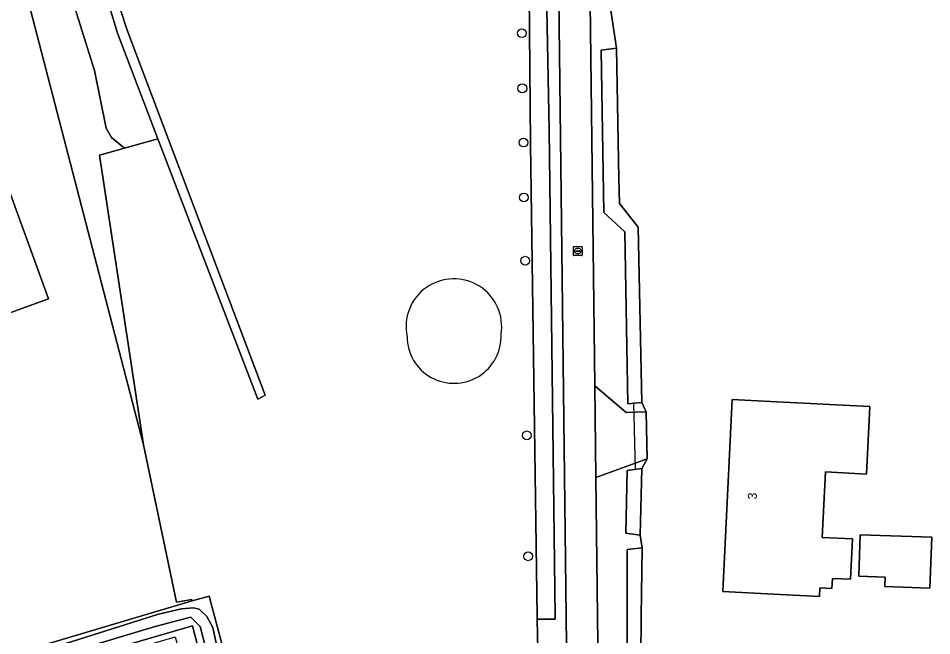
# Model space of a CAD drawing. Extents: x 163859 to 164644, y 379566 to 382155.
# Drawn here: x 164380.2 to 164482.6, y 381497.9 to 381567 of the extents above; entities that cross this region are included whole.
import ezdxf

# ---------------------------------------------------------------- set-up
doc = ezdxf.new("R2010")
doc.units = 0
for name, color, linetype in [('IMGEO_Boom', 7, 'Continuous'), ('IMGEO_Duiker', 7, 'Continuous'), ('IMGEO_Erf', 7, 'Continuous'), ('IMGEO_Grasland_overig', 7, 'Continuous'), ('IMGEO_Groenvoorziening', 7, 'Continuous'), ('IMGEO_Loofbos', 7, 'Continuous'), ('IMGEO_Oever', 7, 'Continuous'), ('IMGEO_Pand', 7, 'Continuous'), ('IMGEO_Pand_nummerreeks', 7, 'Continuous'), ('IMGEO_Rijbaan_lokaal_gesloten', 7, 'Continuous'), ('IMGEO_Rioolput', 7, 'Continuous'), ('IMGEO_Voetpad_open', 7, 'Continuous'), ('IMGEO_Waterloop', 7, 'Continuous')]:
    doc.layers.add(name, color=color, linetype=linetype)

msp = doc.modelspace()

# ---------------------------------------------------------------- linework, layer by layer
at = {"layer": 'IMGEO_Boom'}
for centre in [(164436.63, 381565.35), (164436.69, 381559.18), (164436.82, 381553.1), (164436.86, 381546.96), (164437, 381539.87), (164437.2, 381520.3), (164437.35, 381506.75)]:
    msp.add_circle(centre, 0.489, dxfattribs=at)
at = {"layer": 'IMGEO_Duiker'}
msp.add_lwpolyline([(164449.15, 381523.97), (164449.33, 381516.45)], dxfattribs=at)
at = {"layer": 'IMGEO_Erf'}
for points in [[(164445.79, 381598.85), (164445.76, 381596.44), (164445.96, 381592.66), (164445.85, 381586.66), (164445.92, 381582.44), (164446.04, 381571.66), (164447.24, 381563.68), (164447.52, 381549.09), (164447.58, 381546.29), (164449.66, 381543.61), (164450.08, 381523.98), (164450.55, 381522.92), (164450.68, 381517.67), (164450.07, 381516.57), (164449.91, 381509.12), (164450.1, 381507.69), (164450.01, 381500), (164449.96, 381495.46)], [(164380.24, 381495.98), (164399.71, 381501.75), (164399.68, 381501.92), (164397.93, 381501.62), (164394.23, 381519.23), (164377.05, 381585.25)]]:
    msp.add_lwpolyline(points, dxfattribs=at)
for points in [[(164367.06, 381553.7), (164375.84, 381556.9), (164383.59, 381535.61), (164374.81, 381532.42)], [(164473.46, 381504.17), (164471.43, 381504.27), (164471.38, 381503.14), (164470.04, 381503.2), (164470, 381502.26), (164464.14, 381502.55), (164459.15, 381502.79), (164460.21, 381524.3), (164465.2, 381524.06), (164475.64, 381523.54), (164475.26, 381515.97), (164470.65, 381516.2), (164470.29, 381508.86), (164473.68, 381508.69)], [(164482.36, 381503.18), (164477.29, 381503.36), (164477.33, 381504.41), (164474.39, 381504.51), (164474.55, 381509.16), (164482.56, 381508.89)]]:
    msp.add_lwpolyline(points, close=True, dxfattribs=at)
at = {"layer": 'IMGEO_Grasland_overig'}
for points in [[(164392.11, 381552.47), (164390.65, 381553.68), (164390.08, 381554.71), (164388.77, 381561.19), (164381.76, 381583.47), (164380.51, 381593.56), (164377.23, 381593.05), (164374.37, 381592.06), (164375.48, 381589.55), (164377.05, 381585.25), (164394.23, 381519.23), (164389.32, 381551.69)], [(164403.38, 381480.67), (164403.25, 381483.47), (164403.76, 381484.04), (164404.03, 381484.15), (164403.46, 381487.71), (164402.44, 381487.77), (164402.22, 381489.44), (164399.72, 381498.97), (164381.15, 381493.56), (164378.9, 381492.55), (164376.45, 381492.51), (164374.19, 381493.46), (164372.5, 381495.24), (164367, 381500.41), (164355.98, 381512.51), (164353.09, 381515.54), (164349.7, 381517.97), (164348.35, 381518.62), (164374.92, 381491), (164397.81, 381497.74), (164404.26, 381474.32)]]:
    msp.add_lwpolyline(points, close=True, dxfattribs=at)
at = {"layer": 'IMGEO_Groenvoorziening'}
for points in [[(164443.88, 381602.47), (164444.8, 381525.85), (164448.32, 381522.87), (164450.55, 381522.92), (164450.08, 381523.98), (164448.5, 381523.83), (164448.18, 381543.12), (164445.82, 381545.26), (164445.54, 381563.46), (164447.24, 381563.68), (164446.04, 381571.66)], [(164437.62, 381342.51), (164440.93, 381376.03), (164442.03, 381410.67), (164442.31, 381432.69), (164442.26, 381444.54), (164442.24, 381448.35), (164442.22, 381457.68), (164442.22, 381458.62), (164442.05, 381465.53), (164441.98, 381468.27), (164441.6, 381500), (164440.42, 381600.95)], [(164438.92, 381595.29), (164439.69, 381554.54), (164440.38, 381500), (164440.38, 381499.71), (164438.34, 381499.7), (164438.46, 381494.53)]]:
    msp.add_lwpolyline(points, dxfattribs=at)
for points in [[(164395.86, 381553.52), (164391.32, 381565.35), (164388.89, 381573.41), (164387.77, 381579.05), (164386.14, 381584.23), (164384.86, 381594.48), (164380.51, 381593.56), (164381.76, 381583.47), (164388.77, 381561.19), (164390.08, 381554.71), (164390.65, 381553.68), (164392.11, 381552.47)], [(164448.2, 381486.51), (164447.99, 381488.08), (164447.36, 381488.05), (164447.04, 381496.29), (164448.45, 381496.92), (164448.44, 381500), (164448.42, 381507.52), (164450.1, 381507.69), (164449.91, 381509.12), (164448.27, 381509.34), (164448.43, 381516.36), (164450.07, 381516.57), (164450.68, 381517.67), (164444.92, 381515.57), (164445.11, 381500), (164445.25, 381488.48)]]:
    msp.add_lwpolyline(points, close=True, dxfattribs=at)
for centre, radius, start, end in [((164429.02, 381532.48), 5.36, 350.5628, 192.1236), ((164429.04, 381531.4), 5.27, 180.5064, 2.18)]:
    msp.add_arc(centre, radius, start, end, dxfattribs=at)
at = {"layer": 'IMGEO_Loofbos'}
for points in [[(164438.46, 381494.53), (164438.34, 381499.7), (164438.34, 381500), (164437.6, 381552.99), (164437.24, 381595.18)], [(164388.41, 381582.72), (164390.02, 381574.06), (164391.09, 381569.85), (164392.41, 381565.7), (164407.87, 381524.82), (164407.05, 381524.34), (164395.86, 381553.52), (164392.11, 381552.47), (164389.32, 381551.69), (164394.23, 381519.23), (164397.93, 381501.62), (164399.68, 381501.92), (164399.71, 381501.75), (164401.6, 381502.3), (164404.9, 381489.96), (164405.2, 381487.7), (164404.81, 381487.67), (164403.46, 381487.71), (164404.03, 381484.15)]]:
    msp.add_lwpolyline(points, dxfattribs=at)
for centre, radius, start, end in [((164429.02, 381532.48), 5.36, 350.5628, 192.1236), ((164429.04, 381531.4), 5.27, 180.5064, 2.18)]:
    msp.add_arc(centre, radius, start, end, dxfattribs=at)
at = {"layer": 'IMGEO_Oever'}
for points in [[(164404.9, 381489.96), (164401.6, 381502.3), (164399.71, 381501.75), (164380.24, 381495.98)], [(164381.07, 381495.55), (164392.99, 381499.33), (164395.92, 381500.28), (164398.49, 381500.86), (164399.86, 381500.99), (164400.48, 381500.83), (164401.35, 381500), (164402, 381498.79), (164402.74, 381495.45)], [(164403.46, 381487.71), (164400.58, 381498.87), (164399.54, 381499.92), (164398.09, 381499.57), (164395.31, 381498.82), (164382.41, 381494.93)], [(164381.15, 381493.56), (164399.72, 381498.97), (164402.22, 381489.44)]]:
    msp.add_lwpolyline(points, dxfattribs=at)
at = {"layer": 'IMGEO_Pand'}
for points in [[(164374.81, 381532.42), (164383.59, 381535.61), (164375.84, 381556.9), (164367.06, 381553.7)], [(164470, 381502.26), (164470.04, 381503.2), (164471.38, 381503.14), (164471.43, 381504.27), (164473.46, 381504.17), (164473.68, 381508.69), (164470.29, 381508.86), (164470.65, 381516.2), (164475.26, 381515.97), (164475.64, 381523.54), (164465.2, 381524.06), (164460.21, 381524.3), (164459.15, 381502.79), (164464.14, 381502.55)], [(164474.39, 381504.51), (164477.33, 381504.41), (164477.29, 381503.36), (164482.36, 381503.18), (164482.56, 381508.89), (164474.55, 381509.16)]]:
    msp.add_lwpolyline(points, close=True, dxfattribs=at)
at = {"layer": 'IMGEO_Rijbaan_lokaal_gesloten'}
for points in [[(164445.42, 381474.39), (164445.36, 381478.81), (164445.25, 381488.48), (164445.11, 381500), (164444.92, 381515.57), (164444.8, 381525.85), (164443.88, 381602.47)], [(164440.42, 381600.95), (164441.6, 381500), (164441.98, 381468.27), (164442.05, 381465.53), (164442.22, 381458.62), (164442.22, 381457.68), (164445.79, 381457.7)]]:
    msp.add_lwpolyline(points, dxfattribs=at)
at = {"layer": 'IMGEO_Rioolput'}
for p, q in [((164442.41, 381540.52), (164442.41, 381541.38)), ((164442.48, 381541.45), (164443.33, 381541.45)), ((164442.89, 381541.23), (164442.92, 381541.23)), ((164443.41, 381541.38), (164443.41, 381540.52)), ((164443.33, 381540.45), (164442.48, 381540.45)), ((164442.66, 381540.94), (164442.66, 381540.96)), ((164443.1, 381540.91), (164442.7, 381540.91)), ((164442.71, 381540.99), (164443.1, 381540.99)), ((164442.92, 381540.67), (164442.89, 381540.67)), ((164443.15, 381540.96), (164443.15, 381540.94))]:
    msp.add_line(p, q, dxfattribs=at)
for points in [[(164442.41, 381540.52), (164442.41, 381541.38)], [(164442.48, 381541.45), (164443.33, 381541.45)], [(164443.41, 381541.38), (164443.41, 381540.52)], [(164443.33, 381540.45), (164442.48, 381540.45)]]:
    msp.add_lwpolyline(points, dxfattribs=at)
for centre, radius, start, end in [((164442.48, 381541.37), 0.0765, 91.552, 178.448), ((164442.48, 381541.37), 0.0765, 91.552, 178.448), ((164443.33, 381541.37), 0.0765, 1.552, 88.448), ((164443.33, 381541.37), 0.0765, 1.552, 88.448), ((164442.48, 381540.52), 0.0765, 181.552, 268.448), ((164442.48, 381540.52), 0.0765, 181.552, 268.448), ((164442.7, 381540.95), 0.0403, 85.8775, 175.7526), ((164442.7, 381540.94), 0.0366, 178.938, 274.7102), ((164443.11, 381540.95), 0.0386, 1.7309, 96.639), ((164443.11, 381540.95), 0.043, 264.8664, 352.4533), ((164443.33, 381540.52), 0.0765, 271.552, 358.448), ((164443.33, 381540.52), 0.0765, 271.552, 358.448)]:
    msp.add_arc(centre, radius, start, end, dxfattribs=at)
for centre, major_axis, ratio, start_param, end_param in [((164442.89, 381540.95), (-0.387, 0.002), 0.722429, 4.712389, 7.853982), ((164442.92, 381540.95), (-0.39, 0.002), 0.717154, 1.570796, 4.712389)]:
    msp.add_ellipse(centre, major_axis=major_axis, ratio=ratio, start_param=start_param, end_param=end_param, dxfattribs=at)
at = {"layer": 'IMGEO_Voetpad_open'}
msp.add_lwpolyline([(164444.8, 381525.85), (164444.92, 381515.57), (164450.68, 381517.67), (164450.55, 381522.92), (164448.32, 381522.87)], close=True, dxfattribs=at)
at = {"layer": 'IMGEO_Waterloop'}
for points in [[(164437.24, 381595.18), (164437.6, 381552.99), (164438.34, 381500), (164438.34, 381499.7), (164440.38, 381499.71), (164440.38, 381500), (164439.69, 381554.54)], [(164439.69, 381554.54), (164438.92, 381595.29)], [(164387.11, 381582.42), (164387.77, 381579.05), (164388.89, 381573.41), (164391.32, 381565.35), (164395.86, 381553.52), (164407.05, 381524.34), (164407.87, 381524.82), (164392.41, 381565.7), (164391.09, 381569.85), (164390.02, 381574.06), (164388.41, 381582.72)], [(164402.74, 381495.45), (164402, 381498.79), (164401.35, 381500), (164400.48, 381500.83), (164399.86, 381500.99), (164398.49, 381500.86), (164395.92, 381500.28), (164392.99, 381499.33), (164381.07, 381495.55)], [(164382.41, 381494.93), (164395.31, 381498.82), (164398.09, 381499.57), (164399.54, 381499.92), (164400.58, 381498.87), (164403.46, 381487.71)]]:
    msp.add_lwpolyline(points, dxfattribs=at)
for points in [[(164447.52, 381549.09), (164447.24, 381563.68), (164445.54, 381563.46), (164445.82, 381545.26), (164448.18, 381543.12), (164448.5, 381523.83), (164450.08, 381523.98), (164449.66, 381543.61), (164447.58, 381546.29)], [(164450.07, 381516.57), (164448.43, 381516.36), (164448.27, 381509.34), (164449.91, 381509.12)], [(164448.45, 381496.45), (164448.45, 381495.4), (164449.96, 381495.46), (164450.01, 381500), (164450.1, 381507.69), (164448.42, 381507.52), (164448.44, 381500), (164448.45, 381496.92)]]:
    msp.add_lwpolyline(points, close=True, dxfattribs=at)

# ---------------------------------------------------------------- texts
at = {"layer": 'IMGEO_Pand_nummerreeks'}
msp.add_text('3', height=1, rotation=87.189, dxfattribs=at).set_placement((164462.94, 381513.11))

doc.saveas('drawing.dxf')
